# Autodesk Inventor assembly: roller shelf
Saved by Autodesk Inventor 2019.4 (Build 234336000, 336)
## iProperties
Created: 2020-09
Part Number: roller shelf
Document SubType Name: Assembly
Designer: Administrator
Title: roller shelf v31
Author: Administrator
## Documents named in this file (5)
- c:\worker\convert-fusion-r07\tmp\job-1\164\output\files\c50c4620-2026-4653-9277-f8972be5ac5a\roller shelf v31.iam
- c:\worker\convert-fusion-r07\tmp\job-1\164\output\files\c50c4620-2026-4653-9277-f8972be5ac5a\base.ipt
- c:\worker\convert-fusion-r07\tmp\job-1\164\output\files\c50c4620-2026-4653-9277-f8972be5ac5a\side_1.ipt
- c:\worker\convert-fusion-r07\tmp\job-1\164\output\files\c50c4620-2026-4653-9277-f8972be5ac5a\stiffener.ipt
- c:\worker\convert-fusion-r07\tmp\job-1\164\output\files\c50c4620-2026-4653-9277-f8972be5ac5a\slider.ipt
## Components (8 placed, 4 different names)
1. base:1
2. side:1
3. side:3
4. stiffener:1
5. stiffener:3
6. slider:1
7. slider:2
8. stiffener:4
